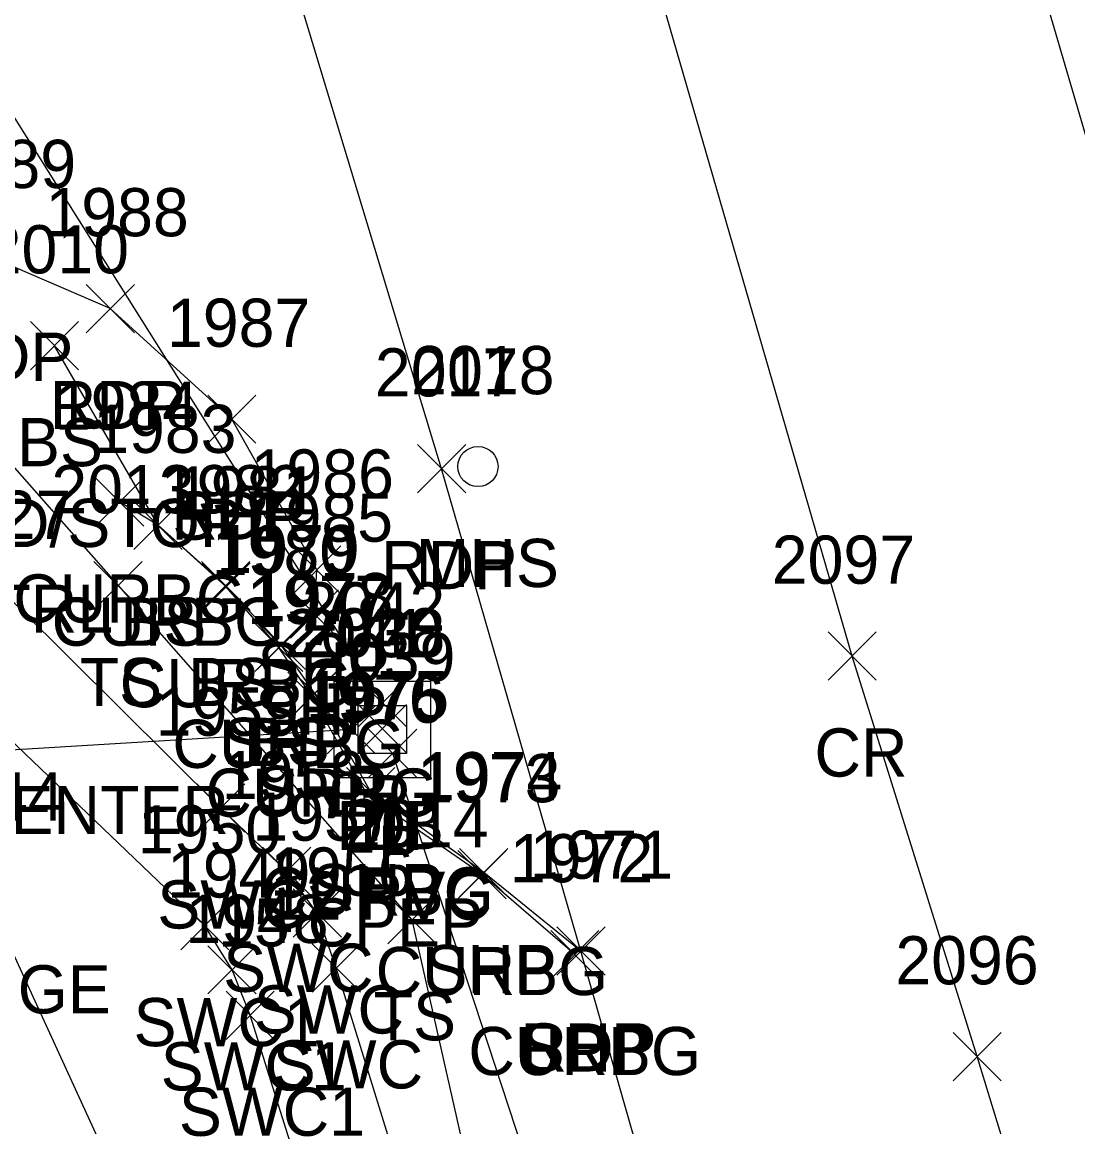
# Model space of a CAD drawing. Extents: x 1620157 to 1620595, y 115111 to 117885.
# Drawn here: x 1620208 to 1620251.82, y 115700.12 to 115745.96 of the extents above; entities that cross this region are included whole.
import ezdxf

# ---------------------------------------------------------------- set-up
doc = ezdxf.new("R2010")
doc.units = 0
for name, color, linetype in [('C_A', 7, 'Continuous'), ('C_C', 7, 'Continuous'), ('D_A', 7, 'Continuous'), ('D_C', 7, 'Continuous'), ('D_I', 7, 'Continuous'), ('D_TIC', 7, 'Continuous'), ('DCP', 7, 'Continuous'), ('DS', 7, 'Continuous'), ('L_A', 7, 'Continuous'), ('L_I', 7, 'Continuous'), ('L_TIC', 7, 'Continuous'), ('LAHR', 7, 'Continuous'), ('LELB', 7, 'Continuous'), ('P_A', 7, 'Continuous'), ('P_I', 7, 'Continuous'), ('P_TIC', 7, 'Continuous'), ('PET', 7, 'Continuous'), ('PRC', 7, 'Continuous'), ('PSP', 7, 'Continuous'), ('R_A', 7, 'Continuous'), ('R_I', 7, 'Continuous'), ('R_TIC', 7, 'Continuous'), ('RC', 7, 'Continuous'), ('RSW', 7, 'Continuous'), ('S_C', 7, 'Continuous'), ('U_A', 7, 'Continuous'), ('U_I', 7, 'Continuous'), ('USMH', 7, 'Continuous')]:
    doc.layers.add(name, color=color, linetype=linetype)

msp = doc.modelspace()

# ---------------------------------------------------------------- linework, layer by layer
at = {"layer": 'D_TIC'}
for points in [[(1620221.949, 115716.713), (1620223.949, 115718.713)], [(1620223.949, 115716.713), (1620221.949, 115718.713)], [(1620220.664, 115715.604), (1620222.664, 115717.604)], [(1620222.664, 115715.604), (1620220.664, 115717.604)], [(1620221.948, 115715.64), (1620223.948, 115717.64)], [(1620223.948, 115715.64), (1620221.948, 115717.64)], [(1620222.378, 115714.616), (1620224.378, 115716.616)], [(1620224.378, 115714.616), (1620222.378, 115716.616)]]:
    msp.add_lwpolyline(points, dxfattribs=at)
at = {"layer": 'DCP'}
for points in [[(1620222.949, 115717.713), (1620188.216, 115772.945)], [(1620221.664, 115716.604), (1620179.437, 115714.054)], [(1620265.107, 115588.482), (1620223.378, 115715.616)]]:
    msp.add_lwpolyline(points, dxfattribs=at)
at = {"layer": 'DS'}
for p, q in [((1620220.945, 115718.606), (1620224.945, 115718.606)), ((1620220.945, 115714.606), (1620220.945, 115718.606)), ((1620224.945, 115718.606), (1620224.945, 115714.606)), ((1620221.945, 115715.606), (1620221.945, 115717.606)), ((1620221.945, 115717.606), (1620223.945, 115717.606)), ((1620223.945, 115717.606), (1620223.945, 115715.606)), ((1620222.95, 115716.607), (1620222.95, 115716.607)), ((1620222.95, 115716.607), (1620222.95, 115716.607)), ((1620223.945, 115715.606), (1620221.945, 115715.606)), ((1620224.945, 115714.606), (1620220.945, 115714.606))]:
    msp.add_line(p, q, dxfattribs=at)
at = {"layer": 'L_TIC'}
for points in [[(1620208.342, 115731.531), (1620210.342, 115733.531)], [(1620210.342, 115731.531), (1620208.342, 115733.531)], [(1620212.638, 115724.082), (1620214.638, 115726.082)], [(1620214.638, 115724.082), (1620212.638, 115726.082)], [(1620210.98, 115721.576), (1620212.98, 115723.576)], [(1620212.98, 115721.576), (1620210.98, 115723.576)], [(1620215.443, 115721.577), (1620217.443, 115723.577)], [(1620217.443, 115721.577), (1620215.443, 115723.577)], [(1620217.758, 115719.094), (1620219.758, 115721.094)], [(1620219.758, 115719.094), (1620217.758, 115721.094)], [(1620223.178, 115707.712), (1620225.178, 115709.712)], [(1620225.178, 115707.712), (1620223.178, 115709.712)]]:
    msp.add_lwpolyline(points, dxfattribs=at)
at = {"layer": 'LAHR'}
msp.add_lwpolyline([(1620213.417, 115694.681), (1620206.467, 115709.825), (1620184.063, 115704.598)], dxfattribs=at)
at = {"layer": 'LELB'}
for points in [[(1620197.795, 115734.316), (1620202.944, 115732.819), (1620211.98, 115722.576), (1620224.178, 115708.712), (1620227.682, 115693.172), (1620232.641, 115674.457)], [(1620218.758, 115720.094), (1620216.443, 115722.577), (1620213.638, 115725.082), (1620209.342, 115732.531)]]:
    msp.add_lwpolyline(points, dxfattribs=at)
at = {"layer": 'P_TIC'}
for points in [[(1620210.658, 115733.07), (1620212.658, 115735.07)], [(1620212.658, 115733.07), (1620210.658, 115735.07)], [(1620215.701, 115728.484), (1620217.701, 115730.484)], [(1620217.701, 115728.484), (1620215.701, 115730.484)], [(1620215.701, 115728.484), (1620217.701, 115730.484)], [(1620217.701, 115728.484), (1620215.701, 115730.484)], [(1620224.409, 115726.426), (1620226.409, 115728.426)], [(1620226.409, 115726.426), (1620224.409, 115728.426)], [(1620219.227, 115722.228), (1620221.227, 115724.228)], [(1620221.227, 115722.228), (1620219.227, 115724.228)], [(1620219.133, 115720.398), (1620221.133, 115722.398)], [(1620221.133, 115720.398), (1620219.133, 115722.398)], [(1620217.758, 115719.094), (1620219.758, 115721.094)], [(1620219.758, 115719.094), (1620217.758, 115721.094)], [(1620241.452, 115718.653), (1620243.452, 115720.653)], [(1620243.452, 115718.653), (1620241.452, 115720.653)], [(1620219.149, 115717.1), (1620221.149, 115719.1)], [(1620221.149, 115717.1), (1620219.149, 115719.1)], [(1620221.461, 115713.029), (1620223.461, 115715.029)], [(1620223.461, 115713.029), (1620221.461, 115715.029)], [(1620226.158, 115709.668), (1620228.158, 115711.668)], [(1620228.158, 115709.668), (1620226.158, 115711.668)], [(1620230.193, 115706.415), (1620232.193, 115708.415)], [(1620232.193, 115706.415), (1620230.193, 115708.415)], [(1620230.193, 115706.415), (1620232.193, 115708.415)], [(1620232.193, 115706.415), (1620230.193, 115708.415)], [(1620246.637, 115702.034), (1620248.637, 115704.034)], [(1620248.637, 115702.034), (1620246.637, 115704.034)]]:
    msp.add_lwpolyline(points, dxfattribs=at)
at = {"layer": 'PET'}
for points in [[(1620336.223, 115456.795), (1620332.523, 115469.32), (1620324.589, 115500.95), (1620318.089, 115527.231), (1620313.062, 115541.759), (1620309.737, 115554.427), (1620302.898, 115574.327), (1620297.627, 115590.435), (1620296.31, 115595.422), (1620295.446, 115598.549), (1620285.025, 115631.411), (1620284.003, 115634.579), (1620271.049, 115676.547), (1620263.941, 115701.458), (1620257.196, 115724.05), (1620247.856, 115755.871), (1620237.557, 115791.502), (1620229.867, 115820.365), (1620222.522, 115845.456)], [(1620320.138, 115439.395), (1620314.873, 115455.055), (1620309.06, 115464.385), (1620304.219, 115479.395), (1620297.094, 115496.088), (1620293.948, 115506.925), (1620292.02, 115512.471), (1620283.673, 115536.019), (1620274.577, 115564.814), (1620268.484, 115584.523), (1620253.11, 115635.23), (1620250.119, 115643.884), (1620242.654, 115668.014), (1620237.662, 115684.194), (1620235.083, 115693.763), (1620231.193, 115707.415), (1620225.409, 115727.426), (1620211.93, 115771.954), (1620203.83, 115799.038), (1620193.365, 115837.216)], [(1620216.701, 115729.484), (1620211.658, 115734.07), (1620206.988, 115736.073), (1620202.022, 115736.645), (1620197.3, 115736.265), (1620194.298, 115735.102), (1620188.021, 115732.001), (1620181.085, 115726.819), (1620172.564, 115719.327)]]:
    msp.add_lwpolyline(points, dxfattribs=at)
at = {"layer": 'PRC'}
msp.add_lwpolyline([(1620328.083, 115447.457), (1620322.143, 115466.609), (1620311.316, 115499.812), (1620303.781, 115522.909), (1620294.725, 115551.741), (1620279.311, 115600.233), (1620271.119, 115626.45), (1620257.914, 115669.486), (1620247.637, 115703.034), (1620242.452, 115719.653), (1620232.976, 115752.347), (1620223.662, 115784.044), (1620214.136, 115816.154), (1620207.469, 115841.181)], dxfattribs=at)
at = {"layer": 'PSP'}
msp.add_lwpolyline([(1620231.193, 115707.415), (1620227.158, 115710.668), (1620222.461, 115714.029), (1620220.149, 115718.1), (1620218.758, 115720.094), (1620220.133, 115721.398), (1620220.227, 115723.228), (1620216.701, 115729.484)], dxfattribs=at)
at = {"layer": 'R_TIC'}
for points in [[(1620211.048, 115725.043), (1620213.048, 115727.043)], [(1620213.048, 115725.043), (1620211.048, 115727.043)], [(1620212.638, 115724.082), (1620214.638, 115726.082)], [(1620214.638, 115724.082), (1620212.638, 115726.082)], [(1620215.464, 115721.528), (1620217.464, 115723.528)], [(1620217.464, 115721.528), (1620215.464, 115723.528)], [(1620217.65, 115719.013), (1620219.65, 115721.013)], [(1620219.65, 115719.013), (1620217.65, 115721.013)], [(1620219.021, 115716.988), (1620221.021, 115718.988)], [(1620221.021, 115716.988), (1620219.021, 115718.988)], [(1620221.329, 115712.888), (1620223.329, 115714.888)], [(1620223.329, 115712.888), (1620221.329, 115714.888)], [(1620215.243, 115712.35), (1620217.243, 115714.35)], [(1620217.243, 115712.35), (1620215.243, 115714.35)], [(1620217.98, 115709.722), (1620219.98, 115711.722)], [(1620219.98, 115709.722), (1620217.98, 115711.722)], [(1620226.087, 115709.588), (1620228.087, 115711.588)], [(1620228.087, 115709.588), (1620226.087, 115711.588)], [(1620219.247, 115707.993), (1620221.247, 115709.993)], [(1620221.247, 115707.993), (1620219.247, 115709.993)], [(1620214.582, 115707.467), (1620216.582, 115709.467)], [(1620216.582, 115707.467), (1620214.582, 115709.467)], [(1620229.936, 115706.267), (1620231.936, 115708.267)], [(1620231.936, 115706.267), (1620229.936, 115708.267)], [(1620215.711, 115705.635), (1620217.711, 115707.635)], [(1620217.711, 115705.635), (1620215.711, 115707.635)], [(1620220.039, 115705.713), (1620222.039, 115707.713)], [(1620222.039, 115705.713), (1620220.039, 115707.713)], [(1620216.463, 115703.749), (1620218.463, 115705.749)], [(1620218.463, 115703.749), (1620216.463, 115705.749)]]:
    msp.add_lwpolyline(points, dxfattribs=at)
at = {"layer": 'RC'}
msp.add_lwpolyline([(1620230.936, 115707.267), (1620227.087, 115710.588), (1620222.329, 115713.888), (1620220.021, 115717.988), (1620218.65, 115720.013), (1620216.464, 115722.528), (1620213.638, 115725.082), (1620212.048, 115726.043)], dxfattribs=at)
at = {"layer": 'RSW'}
for points in [[(1620235.608, 115660.465), (1620229.313, 115680.398), (1620225.918, 115690.945), (1620221.039, 115706.713), (1620220.247, 115708.993), (1620218.98, 115710.722), (1620216.243, 115713.35), (1620201.579, 115727.899), (1620197.914, 115731.583), (1620194.509, 115734.738), (1620191.974, 115731.835), (1620193.114, 115730.36), (1620193.386, 115728.404), (1620192.886, 115726.516), (1620191.873, 115725.229), (1620181.577, 115715.115)], [(1620218.753, 115694.378), (1620220.531, 115695.011), (1620217.463, 115704.749), (1620216.711, 115706.635), (1620215.582, 115708.467), (1620200.617, 115722.765), (1620199.917, 115723.615), (1620198.61, 115723.85), (1620197.008, 115723.537), (1620181.568, 115708.398)]]:
    msp.add_lwpolyline(points, dxfattribs=at)
at = {"layer": 'USMH'}
for p, q in [((1620226.918, 115727.518), (1620226.918, 115727.518)), ((1620227.751, 115727.518), (1620227.751, 115727.518))]:
    msp.add_line(p, q, dxfattribs=at)
msp.add_circle((1620226.918, 115727.518), 0.833, dxfattribs=at)

# ---------------------------------------------------------------- texts
at = {"layer": 'C_A'}
msp.add_text('HVCTRL', height=2, dxfattribs=at).set_placement((1620201.077, 115720.623))
at = {"layer": 'C_C'}
msp.add_text('TIE DIST = 7.66 TO TOP CENTER', height=2, dxfattribs=at).set_placement((1620174.896, 115712.268))
at = {"layer": 'D_A'}
for s, p in [('P', (1620222.327, 115712.713)), ('P', (1620221.042, 115711.604)), ('DIB', (1620221.05, 115711.64)), ('DI', (1620222.005, 115711.607)), ('P', (1620222.756, 115710.616))]:
    msp.add_text(s, height=2, dxfattribs=at).set_placement(p)
at = {"layer": 'D_C'}
for s, p in [('12 PVC', (1620218.28, 115708.713)), ('15 CPEP', (1620216.128, 115707.604))]:
    msp.add_text(s, height=2, dxfattribs=at).set_placement(p)
at = {"layer": 'D_I'}
for s, p in [('2042', (1620219.611, 115720.713)), ('2041', (1620218.892, 115719.604)), ('2040', (1620219.523, 115719.64)), ('2038', (1620219.611, 115719.607)), ('2039', (1620220.032, 115718.616))]:
    msp.add_text(s, height=2, dxfattribs=at).set_placement(p)
at = {"layer": 'L_A'}
for s, p in [('BS', (1620207.783, 115727.531)), ('BS', (1620212.079, 115720.082)), ('TS', (1620210.389, 115717.576)), ('BS', (1620214.884, 115717.577)), ('BS', (1620217.199, 115715.094)), ('HEDGE', (1620202.168, 115704.825)), ('TS', (1620222.588, 115703.712))]:
    msp.add_text(s, height=2, dxfattribs=at).set_placement(p)
at = {"layer": 'L_I'}
for s, p in [('2010', (1620206.484, 115735.531)), ('1983', (1620210.945, 115728.082)), ('2013', (1620209.208, 115725.576)), ('1982', (1620213.751, 115725.577)), ('1979', (1620216.058, 115723.094)), ('1944', (1620203.775, 115712.825)), ('2014', (1620221.407, 115711.712))]:
    msp.add_text(s, height=2, dxfattribs=at).set_placement(p)
at = {"layer": 'P_A'}
for s, p in [('RDP', (1620204.476, 115731.073)), ('RDP', (1620209.146, 115729.07)), ('SHP', (1620214.236, 115724.484)), ('RDP', (1620214.189, 115724.484)), ('RDP', (1620222.897, 115722.426)), ('SHP', (1620217.762, 115718.228)), ('SHP', (1620217.669, 115716.398)), ('SHP', (1620216.294, 115715.094)), ('CR', (1620240.885, 115714.653)), ('SHP', (1620217.685, 115713.1)), ('SHP', (1620219.997, 115709.029)), ('SHP', (1620224.694, 115705.668)), ('SHP', (1620228.729, 115702.415)), ('RDP', (1620228.681, 115702.415))]:
    msp.add_text(s, height=2, dxfattribs=at).set_placement(p)
at = {"layer": 'P_I'}
for s, p in [('1989', (1620204.288, 115739.073)), ('1988', (1620208.965, 115737.07)), ('1987', (1620214.008, 115732.484)), ('1987', (1620214.008, 115732.484)), ('2017', (1620222.638, 115730.426)), ('1986', (1620217.479, 115726.228)), ('1985', (1620217.441, 115724.398)), ('1979', (1620216.058, 115723.094)), ('2097', (1620239.113, 115722.653)), ('1978', (1620217.456, 115721.1)), ('1975', (1620219.769, 115717.029)), ('1974', (1620224.466, 115713.668)), ('1971', (1620229.067, 115710.415)), ('1971', (1620229.067, 115710.415)), ('2096', (1620244.243, 115706.034))]:
    msp.add_text(s, height=2, dxfattribs=at).set_placement(p)
at = {"layer": 'R_A'}
for s, p in [('CURBG', (1620207.63, 115721.043)), ('CURBG', (1620209.22, 115720.082)), ('CURBG', (1620212.047, 115717.528)), ('CURBG', (1620214.233, 115715.013)), ('CURBG', (1620215.604, 115712.988)), ('CURBG', (1620217.912, 115708.888)), ('SWC', (1620213.606, 115708.35)), ('SWC', (1620216.342, 115705.722)), ('CURBG', (1620222.67, 115705.588)), ('SWC', (1620217.609, 115703.993)), ('SWC1', (1620212.622, 115703.467)), ('CURBG', (1620226.518, 115702.267)), ('SWC1', (1620213.75, 115701.635)), ('SWC', (1620218.402, 115701.713)), ('SWC1', (1620214.503, 115699.749))]:
    msp.add_text(s, height=2, dxfattribs=at).set_placement(p)
at = {"layer": 'R_I'}
for s, p in [('1984', (1620209.355, 115729.043)), ('1983', (1620210.945, 115728.082)), ('1981', (1620214.338, 115725.528)), ('1980', (1620215.871, 115723.013)), ('1977', (1620217.329, 115720.988)), ('1976', (1620219.581, 115716.888)), ('1959', (1620213.543, 115716.35)), ('1958', (1620216.287, 115713.722)), ('1973', (1620224.395, 115713.588)), ('1957', (1620217.554, 115711.993)), ('1950', (1620212.803, 115711.467)), ('1972', (1620228.243, 115710.267)), ('1949', (1620214.01, 115709.635)), ('1956', (1620218.291, 115709.713)), ('1948', (1620214.771, 115707.749))]:
    msp.add_text(s, height=2, dxfattribs=at).set_placement(p)
at = {"layer": 'S_C'}
for s, p in [('0050/1307/0627', (1620190.706, 115724.516)), ('GUILFORD CTR RD/STOP', (1620184.466, 115724.178))]:
    msp.add_text(s, height=2, dxfattribs=at).set_placement(p)
at = {"layer": 'U_A'}
msp.add_text('MHS', height=2, dxfattribs=at).set_placement((1620224.335, 115722.518))
at = {"layer": 'U_I'}
msp.add_text('2018', height=2, dxfattribs=at).set_placement((1620224.146, 115730.518))

doc.saveas('drawing.dxf')
